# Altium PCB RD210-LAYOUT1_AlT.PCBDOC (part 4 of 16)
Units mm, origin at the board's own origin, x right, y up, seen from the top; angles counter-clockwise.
Board outline 330 x 300 mm, 6 copper layers (TOP, Mid-Layer 1, Mid-Layer 2, Mid-Layer 3, Mid-Layer 4, BOTTOM), stack 1.422 mm thick; 981 components, 463 nets, 2326 pads, 12534 vias.
Unrouted connection lines stored in the file: 6.
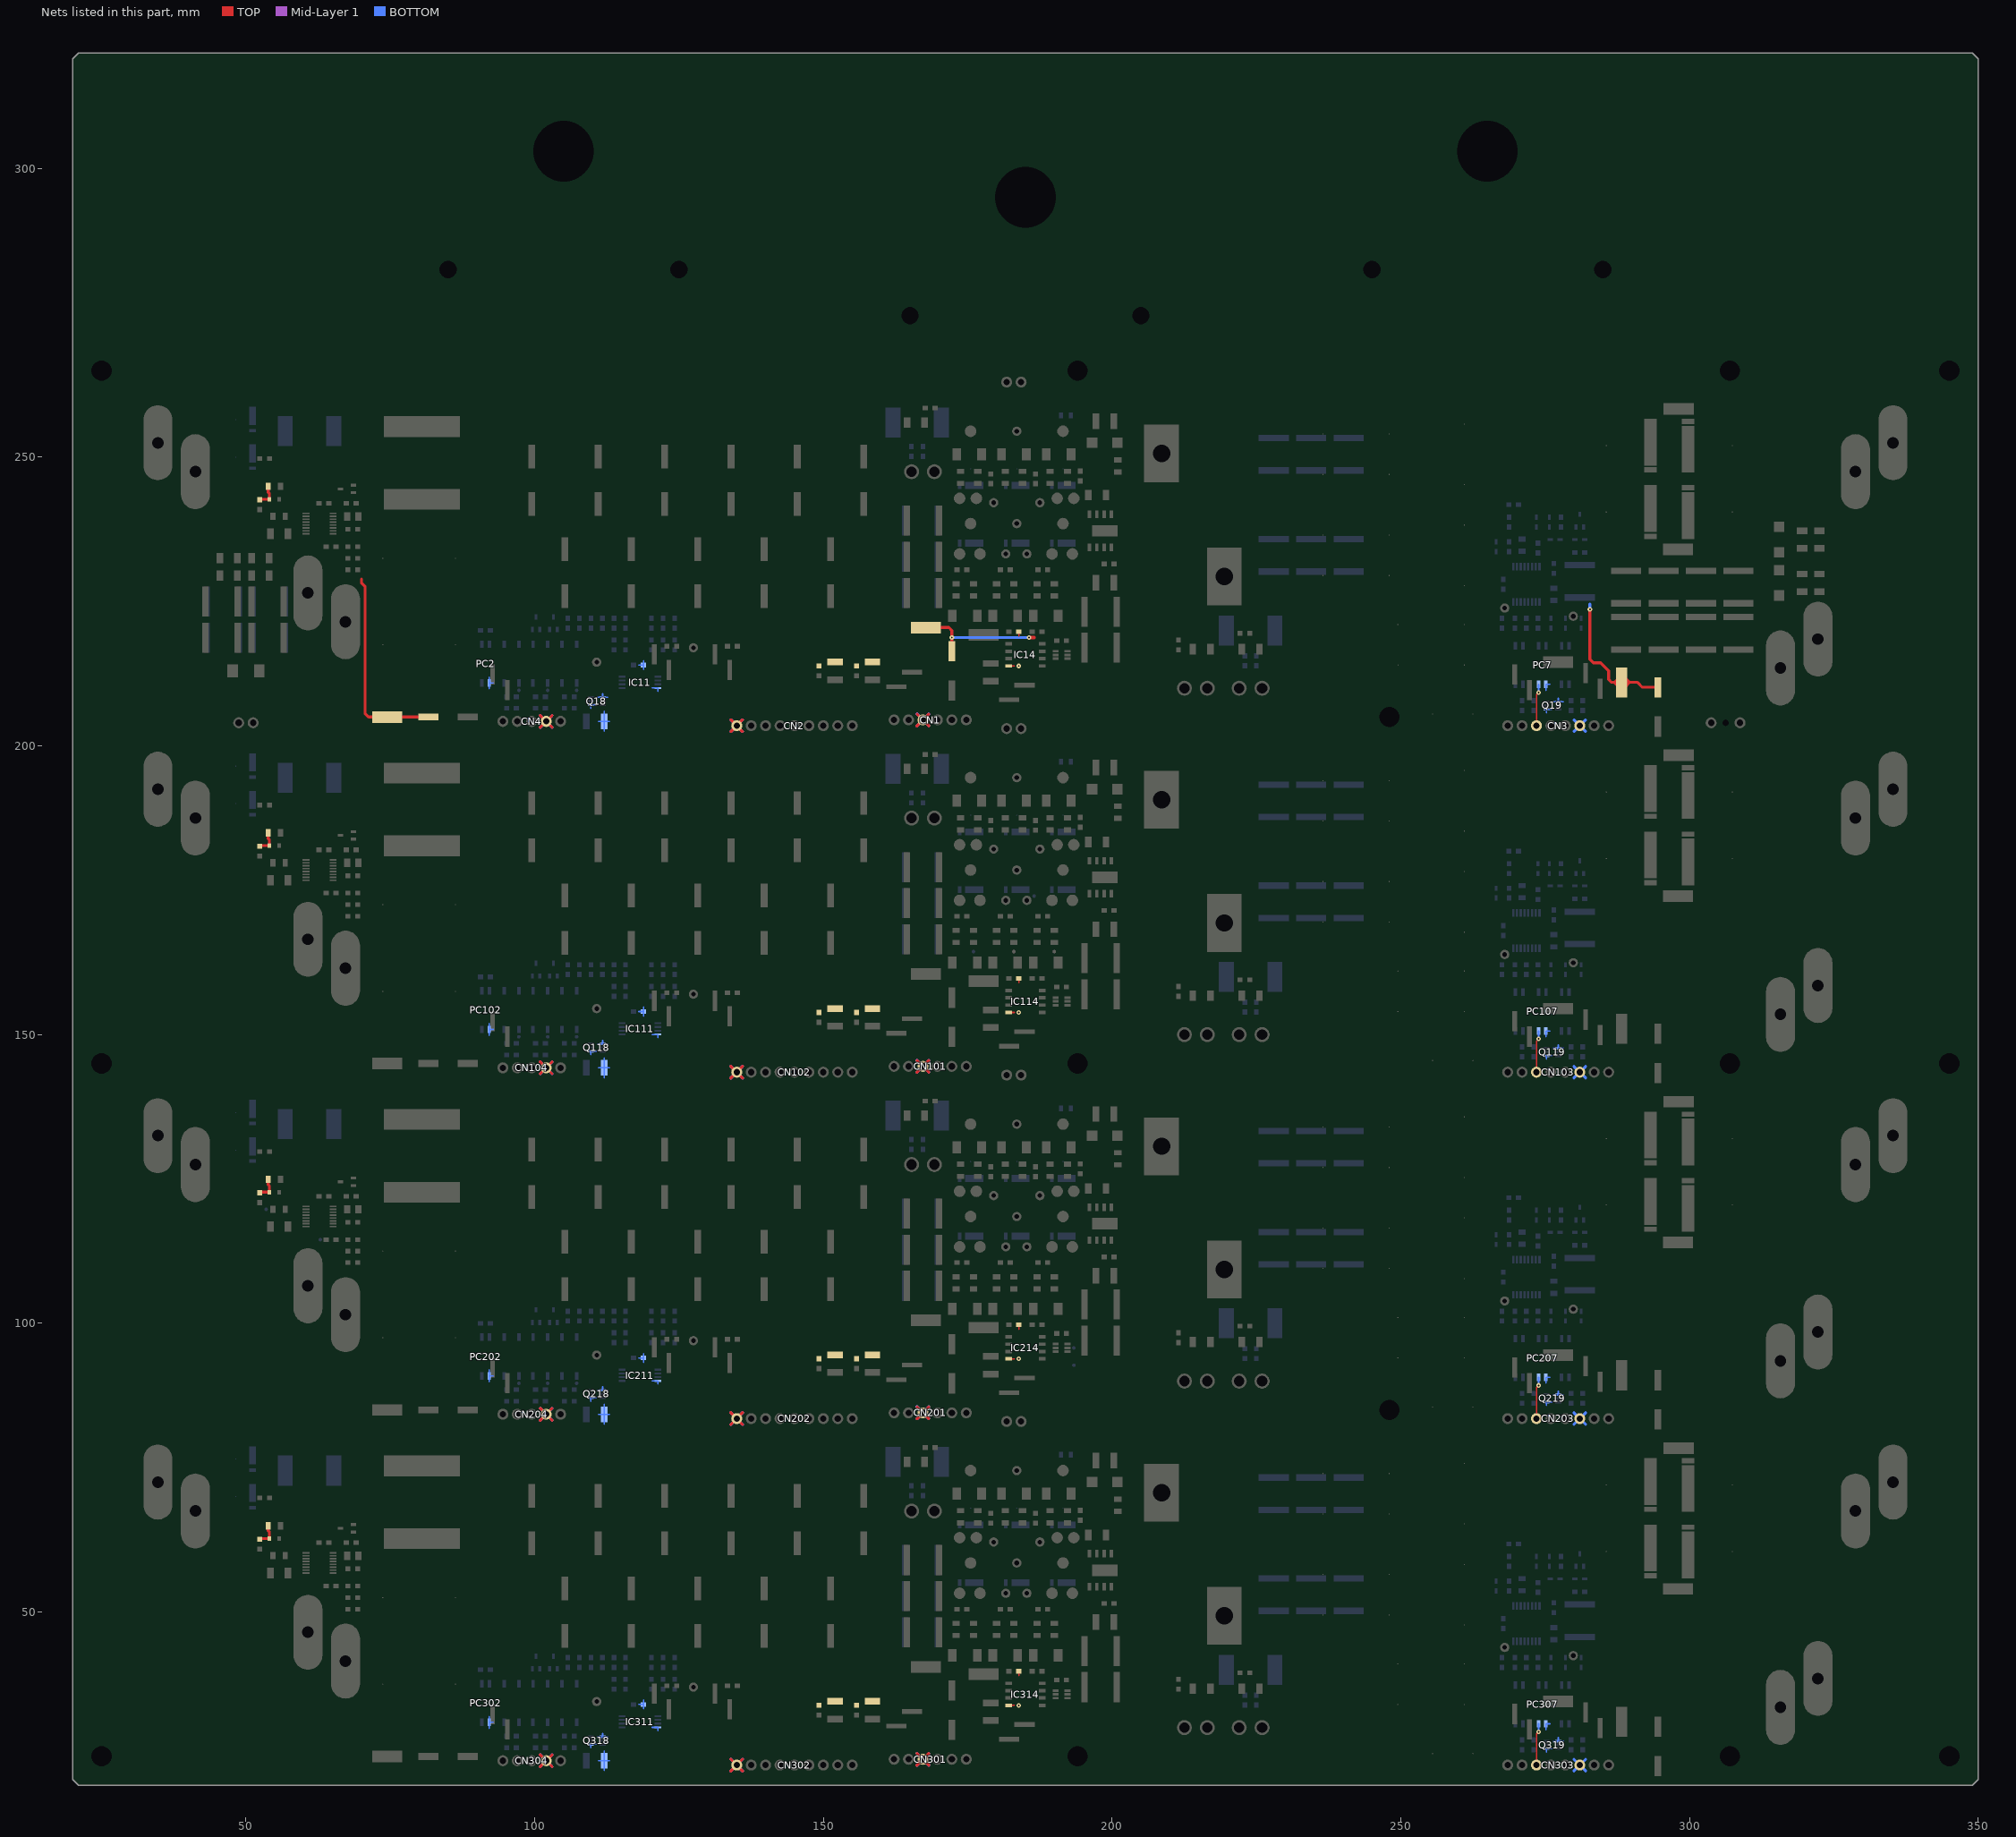
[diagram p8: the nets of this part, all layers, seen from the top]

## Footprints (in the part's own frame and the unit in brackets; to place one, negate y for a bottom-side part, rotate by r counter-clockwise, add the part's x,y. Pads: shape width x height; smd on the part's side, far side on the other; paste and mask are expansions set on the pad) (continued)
S2P_CE-10.3x10.3x12.6-PX11+35 [mm] "KC00080BKP"
  rect 4.1x1.2 smd paste-4.1 mask+0: 1(-4.1,0) 2(4.1,0)
S2P_CE-10.3x10.3x12.6-PX11+36 [mm] "KC00080BKP"
  rect 4.1x1.2 smd paste-4.1 mask+0: 1(-4.1,0) 2(4.1,0)
S2P_CE-10.3x10.3x12.6-PX11+37 [mm] "KC00080BKP"
  rect 4.1x1.2 smd paste-4.1 mask+0: 1(-4.1,0) 2(4.1,0)
S2P_CE-10.3x10.3x12.6-PX11+38 [mm] "KC00080BKP"
  rect 4.1x1.2 smd paste-4.1 mask+0: 1(-4.1,0) 2(4.1,0)
S2P_CE-10.3x10.3x12.6-PX11+39 [mm] "KC00080BKP"
  rect 4.1x1.2 smd paste-4.1 mask+0: 1(-4.1,0) 2(4.1,0)
S2P_CE-10.3x10.3x12.6-PX11+40 [mm] "KC00080BKP"
  rect 4.1x1.2 smd paste-4.1 mask+0: 1(-4.1,0) 2(4.1,0)
S2P_CE-10.3x10.3x12.6-PX11+41 [mm] "KC00080BKP"
  rect 4.1x1.2 smd paste-4.1 mask+0: 1(-4.1,0) 2(4.1,0)
S2P_CE-10.3x10.3x12.6-PX11+42 [mm] "KC00080BKP"
  rect 4.1x1.2 smd paste-4.1 mask+0: 1(-4.1,0) 2(4.1,0)
S2P_CE-10.3x10.3x12.6-PX11+43 [mm] "KC00080BKP"
  rect 4.1x1.2 smd paste-4.1 mask+0: 1(-4.1,0) 2(4.1,0)
S2P_D-3.8x2.4x1-PX4.7 [mm] "KC00080BKP"
  rect 1.5x2.1 smd paste-2.1 mask+0: 1(-2.15,0) 2(2.15,0)
S2P_D-3.8x2.4x1-PX4.7+1 [mm] "KC00080BKP"
  rect 1.5x2.1 smd paste-2.1 mask+0: 1(-2.15,0) 2(2.15,0)
S2P_D-3.8x2.4x1-PX4.7+2 [mm] "KC00080BKP"
  rect 1.5x2.1 smd paste-2.1 mask+0: 1(-2.15,0) 2(2.15,0)
S2P_D-3.8x2.4x1-PX4.7+3 [mm] "KC00080BKP"
  rect 1.5x2.1 smd paste-2.1 mask+0: 1(-2.15,0) 2(2.15,0)
S2P_D-3.8x2.4x1-PX4.7+4 [mm] "KC00080BKP"
  rect 1.5x2.1 smd paste-2.1 mask+0: 1(-2.15,0) 2(2.15,0)
S2P_D-3.8x2.4x1-PX4.7+5 [mm] "KC00080BKP"
  rect 1.5x2.1 smd paste-2.1 mask+0: 1(-2.15,0) 2(2.15,0)
S2P_D-3.8x2.4x1-PX4.7+6 [mm] "KC00080BKP"
  rect 1.5x2.1 smd paste-2.1 mask+0: 1(-2.15,0) 2(2.15,0)
S2P_D-3.8x2.4x1-PX4.7+7 [mm] "KC00080BKP"
  rect 1.5x2.1 smd paste-2.1 mask+0: 1(-2.15,0) 2(2.15,0)
S2P_D-3.8x2.4x1-PX4.7+8 [mm] "KC00080BKP"
  rect 1.5x2.1 smd paste-2.1 mask+0: 1(-2.15,0) 2(2.15,0)
S2P_D-3.8x2.4x1-PX4.7+9 [mm] "KC00080BKP"
  rect 1.5x2.1 smd paste-2.1 mask+0: 1(-2.15,0) 2(2.15,0)
S2P_D-3.8x2.4x1-PX4.7+10 [mm] "KC00080BKP"
  rect 1.5x2.1 smd paste-2.1 mask+0: 1(-2.15,0) 2(2.15,0)
S2P_D-3.8x2.4x1-PX4.7+11 [mm] "KC00080BKP"
  rect 1.5x2.1 smd paste-2.1 mask+0: 1(-2.15,0) 2(2.15,0)
S2P_D-3.8x2.4x1-PX4.7+12 [mm] "KC00080BKP"
  rect 1.5x2.1 smd paste-2.1 mask+0: 1(-2.15,0) 2(2.15,0)
S2P_D-3.8x2.4x1-PX4.7+13 [mm] "KC00080BKP"
  rect 1.5x2.1 smd paste-2.1 mask+0: 1(-2.15,0) 2(2.15,0)
S2P_D-3.8x2.4x1-PX4.7+14 [mm] "KC00080BKP"
  rect 1.5x2.1 smd paste-2.1 mask+0: 1(-2.15,0) 2(2.15,0)
S2P_D-3.8x2.4x1-PX4.7+15 [mm] "KC00080BKP"
  rect 1.5x2.1 smd paste-2.1 mask+0: 1(-2.15,0) 2(2.15,0)
S2P_D-3.8x2.4x1-PX4.7+16 [mm] "KC00080BKP"
  rect 1.5x2.1 smd paste-2.1 mask+0: 1(-2.15,0) 2(2.15,0)
S2P_D-3.8x2.4x1-PX4.7+17 [mm] "KC00080BKP"
  rect 1.5x2.1 smd paste-2.1 mask+0: 1(-2.15,0) 2(2.15,0)
S2P_D-3.8x2.4x1-PX4.7+18 [mm] "KC00080BKP"
  rect 1.5x2.1 smd paste-2.1 mask+0: 1(-2.15,0) 2(2.15,0)
S2P_D-3.8x2.4x1-PX4.7+19 [mm] "KC00080BKP"
  rect 1.5x2.1 smd paste-2.1 mask+0: 1(-2.15,0) 2(2.15,0)
S2P_D-3.8x2.4x1-PX4.7+20 [mm] "KC00080BKP"
  rect 1.5x2.1 smd paste-2.1 mask+0: 1(-2.15,0) 2(2.15,0)
S2P_D-3.8x2.4x1-PX4.7+21 [mm] "KC00080BKP"
  rect 1.5x2.1 smd paste-2.1 mask+0: 1(-2.15,0) 2(2.15,0)
S2P_D-3.8x2.4x1-PX4.7+22 [mm] "KC00080BKP"
  rect 1.5x2.1 smd paste-2.1 mask+0: 1(-2.15,0) 2(2.15,0)
S2P_D-3.8x2.4x1-PX4.7+23 [mm] "KC00080BKP"
  rect 1.5x2.1 smd paste-2.1 mask+0: 1(-2.15,0) 2(2.15,0)
S2P_D-4.3x3.6x2.45-PX5.4 [mm] "KC00080BKP"
  rect 1.8x2.2 smd paste-2.2 mask+0: 1(-2.3,0) 2(2.3,0)
S2P_D-4.32x2.6x2.2-PX5.21 [mm] "KC00080BKP"
  rect 1.8x1.8 smd paste-1.8 mask+0: 1(-2.2,0) 2(2.2,0)
S2P_D-4.32x2.6x2.2-PX5.21+1 [mm] "KC00080BKP"
  rect 1.8x1.8 smd paste-1.8 mask+0: 1(-2.2,0) 2(2.2,0)
S2P_D-4.32x2.6x2.2-PX5.21+2 [mm] "KC00080BKP"
  rect 1.8x1.8 smd paste-1.8 mask+0: 1(-2.2,0) 2(2.2,0)
S2P_D-4.32x2.6x2.2-PX5.21+3 [mm] "KC00080BKP"
  rect 1.8x1.8 smd paste-1.8 mask+0: 1(-2.2,0) 2(2.2,0)
S2P_R-1.6x0.8x0.45-PX1.6 [mm] "KC00080BKP"
  rect 0.9x0.8 smd paste-0.9 mask+0: 1(-0.85,0) 2(0.85,0)
S2P_R-1.6x0.8x0.45-PX1.6+1 [mm] "KC00080BKP"
  rect 0.9x0.8 smd paste-0.9 mask+0: 1(-0.85,0) 2(0.85,0)
S2P_R-1.6x0.8x0.45-PX1.6+2 [mm] "KC00080BKP"
  rect 0.9x0.8 smd paste-0.9 mask+0: 1(-0.85,0) 2(0.85,0)
S2P_R-1.6x0.8x0.45-PX1.6+3 [mm] "KC00080BKP"
  rect 0.9x0.8 smd paste-0.9 mask+0: 1(-0.85,0) 2(0.85,0)
S2P_R-1.6x0.8x0.45-PX1.6+4 [mm] "KC00080BKP"
  rect 0.9x0.8 smd paste-0.9 mask+0: 1(-0.85,0) 2(0.85,0)
S2P_R-1.6x0.8x0.45-PX1.6+5 [mm] "KC00080BKP"
  rect 0.9x0.8 smd paste-0.9 mask+0: 1(-0.85,0) 2(0.85,0)
S2P_R-1.6x0.8x0.45-PX1.6+6 [mm] "KC00080BKP"
  rect 0.9x0.8 smd paste-0.9 mask+0: 1(-0.85,0) 2(0.85,0)
S2P_R-1.6x0.8x0.45-PX1.6+7 [mm] "KC00080BKP"
  rect 0.9x0.8 smd paste-0.9 mask+0: 1(-0.85,0) 2(0.85,0)
S2P_R-1.6x0.8x0.45-PX1.6+8 [mm] "KC00080BKP"
  rect 0.9x0.8 smd paste-0.9 mask+0: 1(-0.85,0) 2(0.85,0)
S2P_R-1.6x0.8x0.45-PX1.6+9 [mm] "KC00080BKP"
  rect 0.9x0.8 smd paste-0.9 mask+0: 1(-0.85,0) 2(0.85,0)
S2P_R-1.6x0.8x0.45-PX1.6+10 [mm] "KC00080BKP"
  rect 0.9x0.8 smd paste-0.9 mask+0: 1(-0.85,0) 2(0.85,0)
S2P_R-1.6x0.8x0.45-PX1.6+11 [mm] "KC00080BKP"
  rect 0.9x0.8 smd paste-0.9 mask+0: 1(-0.85,0) 2(0.85,0)
S2P_R-1.6x0.8x0.45-PX1.6+12 [mm] "KC00080BKP"
  rect 0.9x0.8 smd paste-0.9 mask+0: 1(0.85,0) 2(-0.85,0)
S2P_R-1.6x0.8x0.45-PX1.6+13 [mm] "KC00080BKP"
  rect 0.9x0.8 smd paste-0.9 mask+0: 1(0.85,0) 2(-0.85,0)
S2P_R-1.6x0.8x0.45-PX1.6+14 [mm] "KC00080BKP"
  rect 0.9x0.8 smd paste-0.9 mask+0: 1(0.85,0) 2(-0.85,0)
S2P_R-1.6x0.8x0.45-PX1.6+15 [mm] "KC00080BKP"
  rect 0.9x0.8 smd paste-0.9 mask+0: 1(0.85,0) 2(-0.85,0)
S2P_R-1.6x0.8x0.45-PX1.6+16 [mm] "KC00080BKP"
  rect 0.9x0.8 smd paste-0.9 mask+0: 1(0.85,0) 2(-0.85,0)
S2P_R-1.6x0.8x0.45-PX1.6+17 [mm] "KC00080BKP"
  rect 0.9x0.8 smd paste-0.9 mask+0: 1(0.85,0) 2(-0.85,0)
S2P_R-1.6x0.8x0.45-PX1.6+18 [mm] "KC00080BKP"
  rect 0.9x0.8 smd paste-0.9 mask+0: 1(0.85,0) 2(-0.85,0)
S2P_R-1.6x0.8x0.45-PX1.6+19 [mm] "KC00080BKP"
  rect 0.9x0.8 smd paste-0.9 mask+0: 1(0.85,0) 2(-0.85,0)
S2P_R-1.6x0.8x0.45-PX1.6+20 [mm] "KC00080BKP"
  rect 0.9x0.8 smd paste-0.9 mask+0: 1(0.85,0) 2(-0.85,0)
S2P_R-1.6x0.8x0.45-PX1.6+21 [mm] "KC00080BKP"
  rect 0.9x0.8 smd paste-0.9 mask+0: 1(0.85,0) 2(-0.85,0)
S2P_R-1.6x0.8x0.45-PX1.6+22 [mm] "KC00080BKP"
  rect 0.9x0.8 smd paste-0.9 mask+0: 1(0.85,0) 2(-0.85,0)
S2P_R-1.6x0.8x0.45-PX1.6+23 [mm] "KC00080BKP"
  rect 0.9x0.8 smd paste-0.9 mask+0: 1(0.85,0) 2(-0.85,0)
S2P_R-1.6x0.8x0.45-PX1.6+24 [mm] "KC00080BKP"
  rect 0.9x0.8 smd paste-0.9 mask+0: 1(0.85,0) 2(-0.85,0)
S2P_R-1.6x0.8x0.45-PX1.6+25 [mm] "KC00080BKP"
  rect 0.9x0.8 smd paste-0.9 mask+0: 1(0.85,0) 2(-0.85,0)
S2P_R-1.6x0.8x0.45-PX1.6+26 [mm] "KC00080BKP"
  rect 0.9x0.8 smd paste-0.9 mask+0: 1(0.85,0) 2(-0.85,0)
S2P_R-1.6x0.8x0.45-PX1.6+27 [mm] "KC00080BKP"
  rect 0.9x0.8 smd paste-0.9 mask+0: 1(0.85,0) 2(-0.85,0)
S2P_R-1.6x0.8x0.45-PX1.6+28 [mm] "KC00080BKP"
  rect 0.9x0.8 smd paste-0.9 mask+0: 1(0.85,0) 2(-0.85,0)
S2P_R-1.6x0.8x0.45-PX1.6+29 [mm] "KC00080BKP"
  rect 0.9x0.8 smd paste-0.9 mask+0: 1(0.85,0) 2(-0.85,0)
S2P_R-1.6x0.8x0.45-PX1.6+30 [mm] "KC00080BKP"
  rect 0.9x0.8 smd paste-0.9 mask+0: 1(0.85,0) 2(-0.85,0)
S2P_R-1.6x0.8x0.45-PX1.6+31 [mm] "KC00080BKP"
  rect 0.9x0.8 smd paste-0.9 mask+0: 1(0.85,0) 2(-0.85,0)
S2P_R-1.6x0.8x0.45-PX1.6+32 [mm] "KC00080BKP"
  rect 0.9x0.8 smd paste-0.9 mask+0: 1(0.85,0) 2(-0.85,0)
S2P_R-1.6x0.8x0.45-PX1.6+33 [mm] "KC00080BKP"
  rect 0.9x0.8 smd paste-0.9 mask+0: 1(0.85,0) 2(-0.85,0)
S2P_R-1.6x0.8x0.45-PX1.6+34 [mm] "KC00080BKP"
  rect 0.9x0.8 smd paste-0.9 mask+0: 1(0.85,0) 2(-0.85,0)
S2P_R-1.6x0.8x0.45-PX1.6+35 [mm] "KC00080BKP"
  rect 0.9x0.8 smd paste-0.9 mask+0: 1(0.85,0) 2(-0.85,0)
S2P_R-1.6x0.8x0.45-PX1.6+36 [mm] "KC00080BKP"
  rect 0.9x0.8 smd paste-0.9 mask+0: 1(0.85,0) 2(-0.85,0)
S2P_R-1.6x0.8x0.45-PX1.6+37 [mm] "KC00080BKP"
  rect 0.9x0.8 smd paste-0.9 mask+0: 1(0.85,0) 2(-0.85,0)
S2P_R-1.6x0.8x0.45-PX1.6+38 [mm] "KC00080BKP"
  rect 0.9x0.8 smd paste-0.9 mask+0: 1(0.85,0) 2(-0.85,0)
S2P_R-1.6x0.8x0.45-PX1.6+39 [mm] "KC00080BKP"
  rect 0.9x0.8 smd paste-0.9 mask+0: 1(0.85,0) 2(-0.85,0)
S2P_R-1.6x0.8x0.45-PX1.6+40 [mm] "KC00080BKP"
  rect 0.9x0.8 smd paste-0.9 mask+0: 1(0.85,0) 2(-0.85,0)
S2P_R-1.6x0.8x0.45-PX1.6+41 [mm] "KC00080BKP"
  rect 0.9x0.8 smd paste-0.9 mask+0: 1(0.85,0) 2(-0.85,0)
S2P_R-1.6x0.8x0.45-PX1.6+42 [mm] "KC00080BKP"
  rect 0.9x0.8 smd paste-0.9 mask+0: 1(0.85,0) 2(-0.85,0)
S2P_R-1.6x0.8x0.45-PX1.6+43 [mm] "KC00080BKP"
  rect 0.9x0.8 smd paste-0.9 mask+0: 1(0.85,0) 2(-0.85,0)
S2P_R-1.6x0.8x0.45-PX1.6+44 [mm] "KC00080BKP"
  rect 0.9x0.8 smd paste-0.9 mask+0: 1(0.85,0) 2(-0.85,0)
S2P_R-1.6x0.8x0.45-PX1.6+45 [mm] "KC00080BKP"
  rect 0.9x0.8 smd paste-0.9 mask+0: 1(0.85,0) 2(-0.85,0)
S2P_R-1.6x0.8x0.45-PX1.6+46 [mm] "KC00080BKP"
  rect 0.9x0.8 smd paste-0.9 mask+0: 1(0.85,0) 2(-0.85,0)
S2P_R-1.6x0.8x0.45-PX1.6+47 [mm] "KC00080BKP"
  rect 0.9x0.8 smd paste-0.9 mask+0: 1(0.85,0) 2(-0.85,0)
S2P_R-1.6x0.8x0.45-PX1.6+48 [mm] "KC00080BKP"
  rect 0.9x0.8 smd paste-0.9 mask+0: 1(0.85,0) 2(-0.85,0)
S2P_R-1.6x0.8x0.45-PX1.6+49 [mm] "KC00080BKP"
  rect 0.9x0.8 smd paste-0.9 mask+0: 1(0.85,0) 2(-0.85,0)
S2P_R-1.6x0.8x0.45-PX1.6+50 [mm] "KC00080BKP"
  rect 0.9x0.8 smd paste-0.9 mask+0: 1(0.85,0) 2(-0.85,0)
S2P_R-1.6x0.8x0.45-PX1.6+51 [mm] "KC00080BKP"
  rect 0.9x0.8 smd paste-0.9 mask+0: 1(0.85,0) 2(-0.85,0)
S2P_R-1.6x0.8x0.45-PX1.6+52 [mm] "KC00080BKP"
  rect 0.9x0.8 smd paste-0.9 mask+0: 1(0.85,0) 2(-0.85,0)
S2P_R-1.6x0.8x0.45-PX1.6+53 [mm] "KC00080BKP"
  rect 0.9x0.8 smd paste-0.9 mask+0: 1(0.85,0) 2(-0.85,0)
S2P_R-1.6x0.8x0.45-PX1.6+54 [mm] "KC00080BKP"
  rect 0.9x0.8 smd paste-0.9 mask+0: 1(0.85,0) 2(-0.85,0)
S2P_R-1.6x0.8x0.45-PX1.6+55 [mm] "KC00080BKP"
  rect 0.9x0.8 smd paste-0.9 mask+0: 1(0.85,0) 2(-0.85,0)
S2P_R-1.6x0.8x0.45-PX1.6+56 [mm] "KC00080BKP"
  rect 0.9x0.8 smd paste-0.9 mask+0: 1(-0.85,0) 2(0.85,0)
S2P_R-1.6x0.8x0.45-PX1.6+57 [mm] "KC00080BKP"
  rect 0.9x0.8 smd paste-0.9 mask+0: 1(-0.85,0) 2(0.85,0)
S2P_R-1.6x0.8x0.45-PX1.6+58 [mm] "KC00080BKP"
  rect 0.9x0.8 smd paste-0.9 mask+0: 1(-0.85,0) 2(0.85,0)
S2P_R-1.6x0.8x0.45-PX1.6+59 [mm] "KC00080BKP"
  rect 0.9x0.8 smd paste-0.9 mask+0: 1(-0.85,0) 2(0.85,0)
S2P_R-2x1.25x0.5-PX2 [mm] "KC00080BKP"
  rect 0.9x1.25 smd paste-1.25 mask+0: 1(-1.05,0) 2(1.05,0)
S2P_R-2x1.25x0.5-PX2+1 [mm] "KC00080BKP"
  rect 0.9x1.25 smd paste-1.25 mask+0: 1(-1.05,0) 2(1.05,0)
S2P_R-2x1.25x0.5-PX2+2 [mm] "KC00080BKP"
  rect 0.9x1.25 smd paste-1.25 mask+0: 1(-1.05,0) 2(1.05,0)
S2P_R-2x1.25x0.5-PX2+3 [mm] "KC00080BKP"
  rect 0.9x1.25 smd paste-1.25 mask+0: 1(-1.05,0) 2(1.05,0)
S2P_R-2x1.25x0.5-PX2+4 [mm] "KC00080BKP"
  rect 0.9x1.25 smd paste-1.25 mask+0: 1(-1.05,0) 2(1.05,0)
S2P_R-2x1.25x0.5-PX2+5 [mm] "KC00080BKP"
  rect 0.9x1.25 smd paste-1.25 mask+0: 1(-1.05,0) 2(1.05,0)
S2P_R-2x1.25x0.5-PX2+6 [mm] "KC00080BKP"
  rect 0.9x1.25 smd paste-1.25 mask+0: 1(-1.05,0) 2(1.05,0)
S2P_R-2x1.25x0.5-PX2+7 [mm] "KC00080BKP"
  rect 0.9x1.25 smd paste-1.25 mask+0: 1(-1.05,0) 2(1.05,0)
S2P_R-10x5.2x1.3-PX10 [mm] "KC00080BKP"
  rect 2.6x5.2 smd paste-5.2 mask+0: 1(4.2,0) 2(-4.2,0)
S2P_R-10x5.2x1.3-PX10+1 [mm] "KC00080BKP"
  rect 2.6x5.2 smd paste-5.2 mask+0: 1(4.2,0) 2(-4.2,0)
S2P_R-10x5.2x1.3-PX10+2 [mm] "KC00080BKP"
  rect 2.6x5.2 smd paste-5.2 mask+0: 1(4.2,0) 2(-4.2,0)
S2P_R-10x5.2x1.3-PX10+3 [mm] "KC00080BKP"
  rect 2.6x5.2 smd paste-5.2 mask+0: 1(4.2,0) 2(-4.2,0)
S2P_R-10x5.2x1.3-PX10+4 [mm] "KC00080BKP"
  rect 2.6x5.2 smd paste-5.2 mask+0: 1(4.2,0) 2(-4.2,0)
S2P_R-10x5.2x1.3-PX10+5 [mm] "KC00080BKP"
  rect 2.6x5.2 smd paste-5.2 mask+0: 1(4.2,0) 2(-4.2,0)
S2P_R-10x5.2x1.3-PX10+6 [mm] "KC00080BKP"
  rect 2.6x5.2 smd paste-5.2 mask+0: 1(4.2,0) 2(-4.2,0)
S2P_R-10x5.2x1.3-PX10+7 [mm] "KC00080BKP"
  rect 2.6x5.2 smd paste-5.2 mask+0: 1(4.2,0) 2(-4.2,0)
S2P_R-10x5.2x1.3-PX10+8 [mm] "KC00080BKP"
  rect 2.6x5.2 smd paste-5.2 mask+0: 1(4.2,0) 2(-4.2,0)
S2P_R-10x5.2x1.3-PX10+9 [mm] "KC00080BKP"
  rect 2.6x5.2 smd paste-5.2 mask+0: 1(4.2,0) 2(-4.2,0)
S2P_R-10x5.2x1.3-PX10+10 [mm] "KC00080BKP"
  rect 2.6x5.2 smd paste-5.2 mask+0: 1(4.2,0) 2(-4.2,0)
S2P_R-10x5.2x1.3-PX10+11 [mm] "KC00080BKP"
  rect 2.6x5.2 smd paste-5.2 mask+0: 1(4.2,0) 2(-4.2,0)
S2P_ZD-0.8x1.2x0.6-PY1.6 [mm] "KC00080BKP"
  rect 0.5x0.9 smd paste-0.9 mask+0: 1(0,0.85) 2(0,-0.85)
S2P_ZD-0.8x1.2x0.6-PY1.6+1 [mm] "KC00080BKP"
  rect 0.5x0.9 smd paste-0.9 mask+0: 1(0,0.85) 2(0,-0.85)
S2P_ZD-0.8x1.2x0.6-PY1.6+2 [mm] "KC00080BKP"
  rect 0.5x0.9 smd paste-0.9 mask+0: 1(0,0.85) 2(0,-0.85)
S2P_ZD-0.8x1.2x0.6-PY1.6+3 [mm] "KC00080BKP"
  rect 0.5x0.9 smd paste-0.9 mask+0: 1(0,0.85) 2(0,-0.85)
S2P_ZD-0.8x1.2x0.6-PY1.6+4 [mm] "KC00080BKP"
  rect 0.5x0.9 smd paste-0.9 mask+0: 1(0,0.85) 2(0,-0.85)
S2P_ZD-0.8x1.2x0.6-PY1.6+5 [mm] "KC00080BKP"
  rect 0.5x0.9 smd paste-0.9 mask+0: 1(0,0.85) 2(0,-0.85)
S2P_ZD-0.8x1.2x0.6-PY1.6+6 [mm] "KC00080BKP"
  rect 0.5x0.9 smd paste-0.9 mask+0: 1(0,0.85) 2(0,-0.85)
S2P_ZD-0.8x1.2x0.6-PY1.6+7 [mm] "KC00080BKP"
  rect 0.5x0.9 smd paste-0.9 mask+0: 1(0,0.85) 2(0,-0.85)
S3P_FET-5x5x1-PX1.27-PY6 [mm] "KC00080BKP"
  round 0.178 smd paste-0.178 mask+0: D(0,0)
  rect 0.6x1.2 smd paste-1.2 mask+0: G(-1.905,2.9)
  rect 3.14x1.2 smd paste-3.14 mask+0: S(0.64,2.9)
S3P_FET-5x5x1-PX1.27-PY6+1 [mm] "KC00080BKP"
  round 0.178 smd paste-0.178 mask+0: D(0,0)
  rect 0.6x1.2 smd paste-1.2 mask+0: G(-1.905,2.9)
  rect 3.14x1.2 smd paste-3.14 mask+0: S(0.64,2.9)
S3P_FET-5x5x1-PX1.27-PY6+2 [mm] "KC00080BKP"
  round 0.178 smd paste-0.178 mask+0: D(0,0)
  rect 0.6x1.2 smd paste-1.2 mask+0: G(-1.905,2.9)
  rect 3.14x1.2 smd paste-3.14 mask+0: S(0.64,2.9)
S3P_FET-5x5x1-PX1.27-PY6+3 [mm] "KC00080BKP"
  round 0.178 smd paste-0.178 mask+0: D(0,0)
  rect 0.6x1.2 smd paste-1.2 mask+0: G(-1.905,2.9)
  rect 3.14x1.2 smd paste-3.14 mask+0: S(0.64,2.9)
S3P_FET-5x5x1-PX1.27-PY6+4 [mm] "KC00080BKP"
  round 0.178 smd paste-0.178 mask+0: D(0,0)
  rect 0.6x1.2 smd paste-1.2 mask+0: G(-1.905,2.9)
  rect 3.14x1.2 smd paste-3.14 mask+0: S(0.64,2.9)
S3P_FET-5x5x1-PX1.27-PY6+5 [mm] "KC00080BKP"
  round 0.178 smd paste-0.178 mask+0: D(0,0)
  rect 0.6x1.2 smd paste-1.2 mask+0: G(-1.905,2.9)
  rect 3.14x1.2 smd paste-3.14 mask+0: S(0.64,2.9)
S3P_FET-5x5x1-PX1.27-PY6+6 [mm] "KC00080BKP"
  round 0.178 smd paste-0.178 mask+0: D(0,0)
  rect 0.6x1.2 smd paste-1.2 mask+0: G(-1.905,2.9)
  rect 3.14x1.2 smd paste-3.14 mask+0: S(0.64,2.9)
S3P_FET-5x5x1-PX1.27-PY6+7 [mm] "KC00080BKP"
  round 0.178 smd paste-0.178 mask+0: D(0,0)
  rect 0.6x1.2 smd paste-1.2 mask+0: G(-1.905,2.9)
  rect 3.14x1.2 smd paste-3.14 mask+0: S(0.64,2.9)
S3P_FET-5x5x1-PX1.27-PY6+8 [mm] "KC00080BKP"
  round 0.178 smd paste-0.178 mask+0: D(0,0)
  rect 0.6x1.2 smd paste-1.2 mask+0: G(-1.905,2.9)
  rect 3.14x1.2 smd paste-3.14 mask+0: S(0.64,2.9)
S3P_FET-5x5x1-PX1.27-PY6+9 [mm] "KC00080BKP"
  round 0.178 smd paste-0.178 mask+0: D(0,0)
  rect 0.6x1.2 smd paste-1.2 mask+0: G(-1.905,2.9)
  rect 3.14x1.2 smd paste-3.14 mask+0: S(0.64,2.9)
S3P_FET-5x5x1-PX1.27-PY6+10 [mm] "KC00080BKP"
  round 0.178 smd paste-0.178 mask+0: D(0,0)
  rect 0.6x1.2 smd paste-1.2 mask+0: G(-1.905,2.9)
  rect 3.14x1.2 smd paste-3.14 mask+0: S(0.64,2.9)
S3P_FET-5x5x1-PX1.27-PY6+11 [mm] "KC00080BKP"
  round 0.178 smd paste-0.178 mask+0: D(0,0)
  rect 0.6x1.2 smd paste-1.2 mask+0: G(-1.905,2.9)
  rect 3.14x1.2 smd paste-3.14 mask+0: S(0.64,2.9)
S3P_FET-5x5x1-PX1.27-PY6+12 [mm] "KC00080BKP"
  round 0.178 smd paste-0.178 mask+0: D(0,0)
  rect 0.6x1.2 smd paste-1.2 mask+0: G(-1.905,2.9)
  rect 3.14x1.2 smd paste-3.14 mask+0: S(0.64,2.9)
S3P_FET-5x5x1-PX1.27-PY6+13 [mm] "KC00080BKP"
  round 0.178 smd paste-0.178 mask+0: D(0,0)
  rect 0.6x1.2 smd paste-1.2 mask+0: G(-1.905,2.9)
  rect 3.14x1.2 smd paste-3.14 mask+0: S(0.64,2.9)
S3P_FET-5x5x1-PX1.27-PY6+14 [mm] "KC00080BKP"
  round 0.178 smd paste-0.178 mask+0: D(0,0)
  rect 0.6x1.2 smd paste-1.2 mask+0: G(-1.905,2.9)
  rect 3.14x1.2 smd paste-3.14 mask+0: S(0.64,2.9)
S3P_FET-5x5x1-PX1.27-PY6+15 [mm] "KC00080BKP"
  round 0.178 smd paste-0.178 mask+0: D(0,0)
  rect 0.6x1.2 smd paste-1.2 mask+0: G(-1.905,2.9)
  rect 3.14x1.2 smd paste-3.14 mask+0: S(0.64,2.9)
S3P_FET-5x5x1-PX1.27-PY6+16 [mm] "KC00080BKP"
  round 0.178 smd paste-0.178 mask+0: D(0,0)
  rect 0.6x1.2 smd paste-1.2 mask+0: G(-1.905,2.9)
  rect 3.14x1.2 smd paste-3.14 mask+0: S(0.64,2.9)
S3P_FET-5x5x1-PX1.27-PY6+17 [mm] "KC00080BKP"
  round 0.178 smd paste-0.178 mask+0: D(0,0)
  rect 0.6x1.2 smd paste-1.2 mask+0: G(-1.905,2.9)
  rect 3.14x1.2 smd paste-3.14 mask+0: S(0.64,2.9)
S3P_FET-5x5x1-PX1.27-PY6+18 [mm] "KC00080BKP"
  round 0.178 smd paste-0.178 mask+0: D(0,0)
  rect 0.6x1.2 smd paste-1.2 mask+0: G(-1.905,2.9)
  rect 3.14x1.2 smd paste-3.14 mask+0: S(0.64,2.9)
S3P_FET-5x5x1-PX1.27-PY6+19 [mm] "KC00080BKP"
  round 0.178 smd paste-0.178 mask+0: D(0,0)
  rect 0.6x1.2 smd paste-1.2 mask+0: G(-1.905,2.9)
  rect 3.14x1.2 smd paste-3.14 mask+0: S(0.64,2.9)
S3P_FET-5x5x1-PX1.27-PY6+20 [mm] "KC00080BKP"
  round 0.178 smd paste-0.178 mask+0: D(0,0)
  rect 0.6x1.2 smd paste-1.2 mask+0: G(-1.905,2.9)
  rect 3.14x1.2 smd paste-3.14 mask+0: S(0.64,2.9)
S3P_FET-5x5x1-PX1.27-PY6+21 [mm] "KC00080BKP"
  round 0.178 smd paste-0.178 mask+0: D(0,0)
  rect 0.6x1.2 smd paste-1.2 mask+0: G(-1.905,2.9)
  rect 3.14x1.2 smd paste-3.14 mask+0: S(0.64,2.9)
S3P_FET-5x5x1-PX1.27-PY6+22 [mm] "KC00080BKP"
  round 0.178 smd paste-0.178 mask+0: D(0,0)
  rect 0.6x1.2 smd paste-1.2 mask+0: G(-1.905,2.9)
  rect 3.14x1.2 smd paste-3.14 mask+0: S(0.64,2.9)
S3P_FET-5x5x1-PX1.27-PY6+23 [mm] "KC00080BKP"
  round 0.178 smd paste-0.178 mask+0: D(0,0)
  rect 0.6x1.2 smd paste-1.2 mask+0: G(-1.905,2.9)
  rect 3.14x1.2 smd paste-3.14 mask+0: S(0.64,2.9)
S3P_FET-5x5x1-PX1.27-PY6+24 [mm] "KC00080BKP"
  round 0.178 smd paste-0.178 mask+0: D(0,0)
  rect 0.6x1.2 smd paste-1.2 mask+0: G(-1.905,2.9)
  rect 3.14x1.2 smd paste-3.14 mask+0: S(0.64,2.9)
S3P_FET-5x5x1-PX1.27-PY6+25 [mm] "KC00080BKP"
  round 0.178 smd paste-0.178 mask+0: D(0,0)
  rect 0.6x1.2 smd paste-1.2 mask+0: G(-1.905,2.9)
  rect 3.14x1.2 smd paste-3.14 mask+0: S(0.64,2.9)
S3P_FET-5x5x1-PX1.27-PY6+26 [mm] "KC00080BKP"
  round 0.178 smd paste-0.178 mask+0: D(0,0)
  rect 0.6x1.2 smd paste-1.2 mask+0: G(-1.905,2.9)
  rect 3.14x1.2 smd paste-3.14 mask+0: S(0.64,2.9)
S3P_FET-5x5x1-PX1.27-PY6+27 [mm] "KC00080BKP"
  round 0.178 smd paste-0.178 mask+0: D(0,0)
  rect 0.6x1.2 smd paste-1.2 mask+0: G(-1.905,2.9)
  rect 3.14x1.2 smd paste-3.14 mask+0: S(0.64,2.9)
S3P_FET-5x5x1-PX1.27-PY6+28 [mm] "KC00080BKP"
  round 0.178 smd paste-0.178 mask+0: D(0,0)
  rect 0.6x1.2 smd paste-1.2 mask+0: G(-1.905,2.9)
  rect 3.14x1.2 smd paste-3.14 mask+0: S(0.64,2.9)
S3P_FET-5x5x1-PX1.27-PY6+29 [mm] "KC00080BKP"
  round 0.178 smd paste-0.178 mask+0: D(0,0)
  rect 0.6x1.2 smd paste-1.2 mask+0: G(-1.905,2.9)
  rect 3.14x1.2 smd paste-3.14 mask+0: S(0.64,2.9)
S3P_FET-5x5x1-PX1.27-PY6+30 [mm] "KC00080BKP"
  round 0.178 smd paste-0.178 mask+0: D(0,0)
  rect 0.6x1.2 smd paste-1.2 mask+0: G(-1.905,2.9)
  rect 3.14x1.2 smd paste-3.14 mask+0: S(0.64,2.9)
S3P_FET-5x5x1-PX1.27-PY6+31 [mm] "KC00080BKP"
  round 0.178 smd paste-0.178 mask+0: D(0,0)
  rect 0.6x1.2 smd paste-1.2 mask+0: G(-1.905,2.9)
  rect 3.14x1.2 smd paste-3.14 mask+0: S(0.64,2.9)
S3P_Q-2.0x1.25x0.9-PX0.65-PY2.1 [mm] "KC00080BKP"
  rect 0.5x0.9 smd paste-0.9 mask+0: 1(0.65,1.1) 2(-0.65,1.1) 3(0,-1.1)
S3P_Q-2.0x1.25x0.9-PX0.65-PY2.1+1 [mm] "KC00080BKP"
  rect 0.5x0.9 smd paste-0.9 mask+0: 1(0.65,1.1) 2(-0.65,1.1) 3(0,-1.1)
S3P_Q-2.0x1.25x0.9-PX0.65-PY2.1+2 [mm] "KC00080BKP"
  rect 0.5x0.9 smd paste-0.9 mask+0: 1(0.65,1.1) 2(-0.65,1.1) 3(0,-1.1)
S3P_Q-2.0x1.25x0.9-PX0.65-PY2.1+3 [mm] "KC00080BKP"
  rect 0.5x0.9 smd paste-0.9 mask+0: 1(0.65,1.1) 2(-0.65,1.1) 3(0,-1.1)
S3P_Q-2x1.7x0.75-PX0.65-2.1 [mm] "KC00080BKP"
  rect 0.5x0.9 smd paste-0.9 mask+0: 1(0.65,1.1) 2(-0.65,1.1) 3(0,-1.1)
S3P_Q-2x1.7x0.75-PX0.65-2.1+1 [mm] "KC00080BKP"
  rect 0.5x0.9 smd paste-0.9 mask+0: 1(0.65,1.1) 2(-0.65,1.1) 3(0,-1.1)
S3P_Q-2x1.7x0.75-PX0.65-2.1+2 [mm] "KC00080BKP"
  rect 0.5x0.9 smd paste-0.9 mask+0: 1(0.65,1.1) 2(-0.65,1.1) 3(0,-1.1)
S3P_Q-2x1.7x0.75-PX0.65-2.1+3 [mm] "KC00080BKP"
  rect 0.5x0.9 smd paste-0.9 mask+0: 1(0.65,1.1) 2(-0.65,1.1) 3(0,-1.1)
S3P_Q-2x1.7x0.75-PX0.65-2.1+4 [mm] "KC00080BKP"
  rect 0.5x0.9 smd paste-0.9 mask+0: 1(0.65,1.1) 2(-0.65,1.1) 3(0,-1.1)
S3P_Q-2x1.7x0.75-PX0.65-2.1+5 [mm] "KC00080BKP"
  rect 0.5x0.9 smd paste-0.9 mask+0: 1(0.65,1.1) 2(-0.65,1.1) 3(0,-1.1)
S3P_Q-2x1.7x0.75-PX0.65-2.1+6 [mm] "KC00080BKP"
  rect 0.5x0.9 smd paste-0.9 mask+0: 1(0.65,1.1) 2(-0.65,1.1) 3(0,-1.1)
S3P_Q-2x1.7x0.75-PX0.65-2.1+7 [mm] "KC00080BKP"
  rect 0.5x0.9 smd paste-0.9 mask+0: 1(0.65,1.1) 2(-0.65,1.1) 3(0,-1.1)
S3P_Q-2x1.7x0.75-PX0.65-2.1+8 [mm] "KC00080BKP"
  rect 0.5x0.9 smd paste-0.9 mask+0: 1(-0.65,-1.1) 2(0.65,-1.1) 3(0,1.1)
S3P_Q-2x1.7x0.75-PX0.65-2.1+9 [mm] "KC00080BKP"
  rect 0.5x0.9 smd paste-0.9 mask+0: 1(-0.65,-1.1) 2(0.65,-1.1) 3(0,1.1)
S3P_Q-2x1.7x0.75-PX0.65-2.1+10 [mm] "KC00080BKP"
  rect 0.5x0.9 smd paste-0.9 mask+0: 1(-0.65,-1.1) 2(0.65,-1.1) 3(0,1.1)
S3P_Q-2x1.7x0.75-PX0.65-2.1+11 [mm] "KC00080BKP"
  rect 0.5x0.9 smd paste-0.9 mask+0: 1(-0.65,-1.1) 2(0.65,-1.1) 3(0,1.1)
S3P_Q-9.9x8.5-2.3-PX1.2-PY11.8 [mm] "KC00080BKP"
  rect 0.9x2.2 smd paste-2.2 mask+0: 1(-4.2,-6.25)
  rect 8.1x2.2 smd paste-8.1 mask+0: 2(0.6,-6.25)
  round 0.178 smd paste-0.178 mask+0: 3(0,1.4)
S3P_Q-9.9x8.5-2.3-PX1.2-PY11.8+1 [mm] "KC00080BKP"
  rect 0.9x2.2 smd paste-2.2 mask+0: 1(-4.2,-6.25)
  rect 8.1x2.2 smd paste-8.1 mask+0: 2(0.6,-6.25)
  round 0.178 smd paste-0.178 mask+0: 3(0,1.4)
S3P_Q-9.9x8.5-2.3-PX1.2-PY11.8+2 [mm] "KC00080BKP"
  rect 0.9x2.2 smd paste-2.2 mask+0: 1(-4.2,-6.25)
  rect 8.1x2.2 smd paste-8.1 mask+0: 2(0.6,-6.25)
  round 0.178 smd paste-0.178 mask+0: 3(0,1.4)
S3P_Q-9.9x8.5-2.3-PX1.2-PY11.8+3 [mm] "KC00080BKP"
  rect 0.9x2.2 smd paste-2.2 mask+0: 1(-4.2,-6.25)
  rect 8.1x2.2 smd paste-8.1 mask+0: 2(0.6,-6.25)
  round 0.178 smd paste-0.178 mask+0: 3(0,1.4)
S3P_Q-9.9x8.5-2.3-PX1.2-PY11.8+4 [mm] "KC00080BKP"
  rect 0.9x2.2 smd paste-2.2 mask+0: 1(-4.2,-6.25)
  rect 8.1x2.2 smd paste-8.1 mask+0: 2(0.6,-6.25)
  round 0.178 smd paste-0.178 mask+0: 3(0,1.4)
S3P_Q-9.9x8.5-2.3-PX1.2-PY11.8+5 [mm] "KC00080BKP"
  rect 0.9x2.2 smd paste-2.2 mask+0: 1(-4.2,-6.25)
  rect 8.1x2.2 smd paste-8.1 mask+0: 2(0.6,-6.25)
  round 0.178 smd paste-0.178 mask+0: 3(0,1.4)
S3P_Q-9.9x8.5-2.3-PX1.2-PY11.8+6 [mm] "KC00080BKP"
  rect 0.9x2.2 smd paste-2.2 mask+0: 1(-4.2,-6.25)
  rect 8.1x2.2 smd paste-8.1 mask+0: 2(0.6,-6.25)
  round 0.178 smd paste-0.178 mask+0: 3(0,1.4)
S3P_Q-9.9x8.5-2.3-PX1.2-PY11.8+7 [mm] "KC00080BKP"
  rect 0.9x2.2 smd paste-2.2 mask+0: 1(-4.2,-6.25)
  rect 8.1x2.2 smd paste-8.1 mask+0: 2(0.6,-6.25)
  round 0.178 smd paste-0.178 mask+0: 3(0,1.4)
S3P_Q-9.9x8.5-2.3-PX1.2-PY11.8+8 [mm] "KC00080BKP"
  rect 0.9x2.2 smd paste-2.2 mask+0: 1(-4.2,-6.25)
  rect 8.1x2.2 smd paste-8.1 mask+0: 2(0.6,-6.25)
  round 0.178 smd paste-0.178 mask+0: 3(0,1.4)
S3P_Q-9.9x8.5-2.3-PX1.2-PY11.8+9 [mm] "KC00080BKP"
  rect 0.9x2.2 smd paste-2.2 mask+0: 1(-4.2,-6.25)
  rect 8.1x2.2 smd paste-8.1 mask+0: 2(0.6,-6.25)
  round 0.178 smd paste-0.178 mask+0: 3(0,1.4)
S3P_Q-9.9x8.5-2.3-PX1.2-PY11.8+10 [mm] "KC00080BKP"
  rect 0.9x2.2 smd paste-2.2 mask+0: 1(-4.2,-6.25)
  rect 8.1x2.2 smd paste-8.1 mask+0: 2(0.6,-6.25)
  round 0.178 smd paste-0.178 mask+0: 3(0,1.4)
S3P_Q-9.9x8.5-2.3-PX1.2-PY11.8+11 [mm] "KC00080BKP"
  rect 0.9x2.2 smd paste-2.2 mask+0: 1(-4.2,-6.25)
  rect 8.1x2.2 smd paste-8.1 mask+0: 2(0.6,-6.25)
  round 0.178 smd paste-0.178 mask+0: 3(0,1.4)
S3P_Q-9.9x8.5-2.3-PX1.2-PY11.8+12 [mm] "KC00080BKP"
  rect 0.9x2.2 smd paste-2.2 mask+0: 1(-4.2,-6.25)
  rect 8.1x2.2 smd paste-8.1 mask+0: 2(0.6,-6.25)
  round 0.178 smd paste-0.178 mask+0: 3(0,1.4)
S3P_Q-9.9x8.5-2.3-PX1.2-PY11.8+13 [mm] "KC00080BKP"
  rect 0.9x2.2 smd paste-2.2 mask+0: 1(-4.2,-6.25)
  rect 8.1x2.2 smd paste-8.1 mask+0: 2(0.6,-6.25)
  round 0.178 smd paste-0.178 mask+0: 3(0,1.4)
S3P_Q-9.9x8.5-2.3-PX1.2-PY11.8+14 [mm] "KC00080BKP"
  rect 0.9x2.2 smd paste-2.2 mask+0: 1(-4.2,-6.25)
  rect 8.1x2.2 smd paste-8.1 mask+0: 2(0.6,-6.25)
  round 0.178 smd paste-0.178 mask+0: 3(0,1.4)
S3P_Q-9.9x8.5-2.3-PX1.2-PY11.8+15 [mm] "KC00080BKP"
  rect 0.9x2.2 smd paste-2.2 mask+0: 1(-4.2,-6.25)
  rect 8.1x2.2 smd paste-8.1 mask+0: 2(0.6,-6.25)
  round 0.178 smd paste-0.178 mask+0: 3(0,1.4)
S4P_PC-2.6x4.55?2.1-PX1.27-PY7 [mm] "KC00080BKP"
  rect 0.6x1.3 smd paste-1.3 mask+0: 1(0.635,3.35) 2(-0.65,3.35) 3(-0.635,-3.35) 4(0.635,-3.35)
S4P_PC-2.6x4.55?2.1-PX1.27-PY7+1 [mm] "KC00080BKP"
  rect 0.6x1.3 smd paste-1.3 mask+0: 1(0.635,3.35) 2(-0.65,3.35) 3(-0.635,-3.35) 4(0.635,-3.35)
S4P_PC-2.6x4.55?2.1-PX1.27-PY7+2 [mm] "KC00080BKP"
  rect 0.6x1.3 smd paste-1.3 mask+0: 1(0.635,3.35) 2(-0.65,3.35) 3(-0.635,-3.35) 4(0.635,-3.35)
S4P_PC-2.6x4.55?2.1-PX1.27-PY7+3 [mm] "KC00080BKP"
  rect 0.6x1.3 smd paste-1.3 mask+0: 1(0.635,3.35) 2(-0.65,3.35) 3(-0.635,-3.35) 4(0.635,-3.35)
S4P_PC-2.6x4.55?2.1-PX1.27-PY7+4 [mm] "KC00080BKP"
  rect 0.6x1.3 smd paste-1.3 mask+0: 1(0.635,3.35) 2(-0.65,3.35) 3(-0.635,-3.35) 4(0.635,-3.35)
S4P_PC-2.6x4.55?2.1-PX1.27-PY7+5 [mm] "KC00080BKP"
  rect 0.6x1.3 smd paste-1.3 mask+0: 1(0.635,3.35) 2(-0.65,3.35) 3(-0.635,-3.35) 4(0.635,-3.35)
S4P_PC-2.6x4.55?2.1-PX1.27-PY7+6 [mm] "KC00080BKP"
  rect 0.6x1.3 smd paste-1.3 mask+0: 1(0.635,3.35) 2(-0.65,3.35) 3(-0.635,-3.35) 4(0.635,-3.35)
S4P_PC-2.6x4.55?2.1-PX1.27-PY7+7 [mm] "KC00080BKP"
  rect 0.6x1.3 smd paste-1.3 mask+0: 1(0.635,3.35) 2(-0.65,3.35) 3(-0.635,-3.35) 4(0.635,-3.35)
S4P_PC-2.6x4.55?2.1-PX1.27-PY7+8 [mm] "KC00080BKP"
  rect 0.6x1.3 smd paste-1.3 mask+0: 1(0.635,3.35) 2(-0.65,3.35) 3(-0.635,-3.35) 4(0.635,-3.35)
S4P_PC-2.6x4.55?2.1-PX1.27-PY7+9 [mm] "KC00080BKP"
  rect 0.6x1.3 smd paste-1.3 mask+0: 1(0.635,3.35) 2(-0.65,3.35) 3(-0.635,-3.35) 4(0.635,-3.35)
S4P_PC-2.6x4.55?2.1-PX1.27-PY7+10 [mm] "KC00080BKP"
  rect 0.6x1.3 smd paste-1.3 mask+0: 1(0.635,3.35) 2(-0.65,3.35) 3(-0.635,-3.35) 4(0.635,-3.35)
S4P_PC-2.6x4.55?2.1-PX1.27-PY7+11 [mm] "KC00080BKP"
  rect 0.6x1.3 smd paste-1.3 mask+0: 1(0.635,3.35) 2(-0.65,3.35) 3(-0.635,-3.35) 4(0.635,-3.35)
S4P_PC-2.6x4.55?2.1-PX1.27-PY7+12 [mm] "KC00080BKP"
  rect 0.6x1.3 smd paste-1.3 mask+0: 1(0.635,3.35) 2(-0.65,3.35) 3(-0.635,-3.35) 4(0.635,-3.35)
S4P_PC-2.6x4.55?2.1-PX1.27-PY7+13 [mm] "KC00080BKP"
  rect 0.6x1.3 smd paste-1.3 mask+0: 1(0.635,3.35) 2(-0.65,3.35) 3(-0.635,-3.35) 4(0.635,-3.35)
S4P_PC-2.6x4.55?2.1-PX1.27-PY7+14 [mm] "KC00080BKP"
  rect 0.6x1.3 smd paste-1.3 mask+0: 1(0.635,3.35) 2(-0.65,3.35) 3(-0.635,-3.35) 4(0.635,-3.35)
S4P_PC-2.6x4.55?2.1-PX1.27-PY7+15 [mm] "KC00080BKP"
  rect 0.6x1.3 smd paste-1.3 mask+0: 1(0.635,3.35) 2(-0.65,3.35) 3(-0.635,-3.35) 4(0.635,-3.35)
S4P_PC-3.7?4.55?2.1-PX2.54-PY7 [mm] "KC00080BKP"
  rect 0.6x1.3 smd paste-1.3 mask+0: 1(1.27,3.35) 3(-1.285,3.35) 4(-1.27,-3.35) 6(1.27,-3.35)
S4P_PC-3.7?4.55?2.1-PX2.54-PY7+1 [mm] "KC00080BKP"
  rect 0.6x1.3 smd paste-1.3 mask+0: 1(1.27,3.35) 3(-1.285,3.35) 4(-1.27,-3.35) 6(1.27,-3.35)
S4P_PC-3.7?4.55?2.1-PX2.54-PY7+2 [mm] "KC00080BKP"
  rect 0.6x1.3 smd paste-1.3 mask+0: 1(1.27,3.35) 3(-1.285,3.35) 4(-1.27,-3.35) 6(1.27,-3.35)
S4P_PC-3.7?4.55?2.1-PX2.54-PY7+3 [mm] "KC00080BKP"
  rect 0.6x1.3 smd paste-1.3 mask+0: 1(1.27,3.35) 3(-1.285,3.35) 4(-1.27,-3.35) 6(1.27,-3.35)
S4P_PC-3.7?4.55?2.1-PX2.54-PY7+4 [mm] "KC00080BKP"
  rect 0.6x1.3 smd paste-1.3 mask+0: 1(1.27,3.35) 3(-1.285,3.35) 4(-1.27,-3.35) 6(1.27,-3.35)
S4P_PC-3.7?4.55?2.1-PX2.54-PY7+5 [mm] "KC00080BKP"
  rect 0.6x1.3 smd paste-1.3 mask+0: 1(1.27,3.35) 3(-1.285,3.35) 4(-1.27,-3.35) 6(1.27,-3.35)
S4P_PC-3.7?4.55?2.1-PX2.54-PY7+6 [mm] "KC00080BKP"
  rect 0.6x1.3 smd paste-1.3 mask+0: 1(1.27,3.35) 3(-1.285,3.35) 4(-1.27,-3.35) 6(1.27,-3.35)
S4P_PC-3.7?4.55?2.1-PX2.54-PY7+7 [mm] "KC00080BKP"
  rect 0.6x1.3 smd paste-1.3 mask+0: 1(1.27,3.35) 3(-1.285,3.35) 4(-1.27,-3.35) 6(1.27,-3.35)
S4P_PC-3.7?4.55?2.1-PX2.54-PY7+8 [mm] "KC00080BKP"
  rect 0.6x1.3 smd paste-1.3 mask+0: 1(1.27,3.35) 3(-1.285,3.35) 4(-1.27,-3.35) 6(1.27,-3.35)
S4P_PC-3.7?4.55?2.1-PX2.54-PY7+9 [mm] "KC00080BKP"
  rect 0.6x1.3 smd paste-1.3 mask+0: 1(1.27,3.35) 3(-1.285,3.35) 4(-1.27,-3.35) 6(1.27,-3.35)
S4P_PC-3.7?4.55?2.1-PX2.54-PY7+10 [mm] "KC00080BKP"
  rect 0.6x1.3 smd paste-1.3 mask+0: 1(1.27,3.35) 3(-1.285,3.35) 4(-1.27,-3.35) 6(1.27,-3.35)
S4P_PC-3.7?4.55?2.1-PX2.54-PY7+11 [mm] "KC00080BKP"
  rect 0.6x1.3 smd paste-1.3 mask+0: 1(1.27,3.35) 3(-1.285,3.35) 4(-1.27,-3.35) 6(1.27,-3.35)
S6P_U-2x1.25x0.95-PX0.65-PY2.1 [mm] "KC00080BKP"
  rect 0.45x1.05 smd paste-1.05 mask+0: 1(0.65,1.025) 2(0,1.025) 3(-0.65,1.025) 4(-0.65,-1.025) 5(0,-1.025) 6(0.65,-1.025)
S6P_U-2x1.25x0.95-PX0.65-PY2.1+1 [mm] "KC00080BKP"
  rect 0.45x1.05 smd paste-1.05 mask+0: 1(0.65,1.025) 2(0,1.025) 3(-0.65,1.025) 4(-0.65,-1.025) 5(0,-1.025) 6(0.65,-1.025)
S6P_U-2x1.25x0.95-PX0.65-PY2.1+2 [mm] "KC00080BKP"
  rect 0.45x1.05 smd paste-1.05 mask+0: 1(0.65,1.025) 2(0,1.025) 3(-0.65,1.025) 4(-0.65,-1.025) 5(0,-1.025) 6(0.65,-1.025)
S6P_U-2x1.25x0.95-PX0.65-PY2.1+3 [mm] "KC00080BKP"
  rect 0.45x1.05 smd paste-1.05 mask+0: 1(0.65,1.025) 2(0,1.025) 3(-0.65,1.025) 4(-0.65,-1.025) 5(0,-1.025) 6(0.65,-1.025)
S6P_U-2x1.25x0.95-PX0.65-PY2.1+4 [mm] "KC00080BKP"
  rect 0.45x1.05 smd paste-1.05 mask+0: 1(0.65,1.025) 2(0,1.025) 3(-0.65,1.025) 4(-0.65,-1.025) 5(0,-1.025) 6(0.65,-1.025)
S6P_U-2x1.25x0.95-PX0.65-PY2.1+5 [mm] "KC00080BKP"
  rect 0.45x1.05 smd paste-1.05 mask+0: 1(0.65,1.025) 2(0,1.025) 3(-0.65,1.025) 4(-0.65,-1.025) 5(0,-1.025) 6(0.65,-1.025)
S6P_U-2x1.25x0.95-PX0.65-PY2.1+6 [mm] "KC00080BKP"
  rect 0.45x1.05 smd paste-1.05 mask+0: 1(0.65,1.025) 2(0,1.025) 3(-0.65,1.025) 4(-0.65,-1.025) 5(0,-1.025) 6(0.65,-1.025)
S6P_U-2x1.25x0.95-PX0.65-PY2.1+7 [mm] "KC00080BKP"
  rect 0.45x1.05 smd paste-1.05 mask+0: 1(0.65,1.025) 2(0,1.025) 3(-0.65,1.025) 4(-0.65,-1.025) 5(0,-1.025) 6(0.65,-1.025)
S8P_U-4.4x3x1.2-PX6.4-PY0.65 [mm] "KC00080BKP"
  rect 1.2x0.35 smd paste-1.2 mask+0: 1(3.1,-0.975) 2(3.1,-0.325) 3(3.1,0.325) 4(3.1,0.975) 5(-3.1,0.975) 6(-3.1,0.325) 7(-3.1,-0.325) 8(-3.1,-0.975)
S8P_U-4.4x3x1.2-PX6.4-PY0.65+1 [mm] "KC00080BKP"
  rect 1.2x0.35 smd paste-1.2 mask+0: 1(3.1,-0.975) 2(3.1,-0.325) 3(3.1,0.325) 4(3.1,0.975) 5(-3.1,0.975) 6(-3.1,0.325) 7(-3.1,-0.325) 8(-3.1,-0.975)
S8P_U-4.4x3x1.2-PX6.4-PY0.65+2 [mm] "KC00080BKP"
  rect 1.2x0.35 smd paste-1.2 mask+0: 1(3.1,-0.975) 2(3.1,-0.325) 3(3.1,0.325) 4(3.1,0.975) 5(-3.1,0.975) 6(-3.1,0.325) 7(-3.1,-0.325) 8(-3.1,-0.975)
S8P_U-4.4x3x1.2-PX6.4-PY0.65+3 [mm] "KC00080BKP"
  rect 1.2x0.35 smd paste-1.2 mask+0: 1(3.1,-0.975) 2(3.1,-0.325) 3(3.1,0.325) 4(3.1,0.975) 5(-3.1,0.975) 6(-3.1,0.325) 7(-3.1,-0.325) 8(-3.1,-0.975)
S8P_U-4.9x3.9x1.75-PX1.27-PY6 [mm] "KC00080BKP"
  rect 0.6x1.2 smd paste-1.2 mask+0: 1(-1.905,-2.9) 2(-0.635,-2.9) 3(0.635,-2.9) 4(1.905,-2.9) 5(1.905,2.9) 6(0.635,2.9) 7(-0.635,2.9) 8(-1.905,2.9)
S8P_U-4.9x3.9x1.75-PX1.27-PY6+1 [mm] "KC00080BKP"
  rect 0.6x1.2 smd paste-1.2 mask+0: 1(-1.905,-2.9) 2(-0.635,-2.9) 3(0.635,-2.9) 4(1.905,-2.9) 5(1.905,2.9) 6(0.635,2.9) 7(-0.635,2.9) 8(-1.905,2.9)
S8P_U-4.9x3.9x1.75-PX1.27-PY6+2 [mm] "KC00080BKP"
  rect 0.6x1.2 smd paste-1.2 mask+0: 1(-1.905,-2.9) 2(-0.635,-2.9) 3(0.635,-2.9) 4(1.905,-2.9) 5(1.905,2.9) 6(0.635,2.9) 7(-0.635,2.9) 8(-1.905,2.9)
S8P_U-4.9x3.9x1.75-PX1.27-PY6+3 [mm] "KC00080BKP"
  rect 0.6x1.2 smd paste-1.2 mask+0: 1(-1.905,-2.9) 2(-0.635,-2.9) 3(0.635,-2.9) 4(1.905,-2.9) 5(1.905,2.9) 6(0.635,2.9) 7(-0.635,2.9) 8(-1.905,2.9)
S9P_U-4.9x3.9x1.7-PX1.27-PY6 [mm] "KC00080BKP"
  rect 0.6x1.3 smd paste-1.3 mask+0: 1(-1.905,-2.85) 2(-0.635,-2.85) 3(0.635,-2.85) 4(1.905,-2.85) 5(1.905,2.85) 6(0.635,2.85) 7(-0.635,2.85) 8(-1.905,2.85)
  rect 4.4x2 smd paste-4.4 mask+0: 9(-0.75,0)
S9P_U-4.9x3.9x1.7-PX1.27-PY6+1 [mm] "KC00080BKP"
  rect 0.6x1.3 smd paste-1.3 mask+0: 1(-1.905,-2.85) 2(-0.635,-2.85) 3(0.635,-2.85) 4(1.905,-2.85) 5(1.905,2.85) 6(0.635,2.85) 7(-0.635,2.85) 8(-1.905,2.85)
  rect 4.4x2 smd paste-4.4 mask+0: 9(-0.75,0)
S9P_U-4.9x3.9x1.7-PX1.27-PY6+2 [mm] "KC00080BKP"
  rect 0.6x1.3 smd paste-1.3 mask+0: 1(-1.905,-2.85) 2(-0.635,-2.85) 3(0.635,-2.85) 4(1.905,-2.85) 5(1.905,2.85) 6(0.635,2.85) 7(-0.635,2.85) 8(-1.905,2.85)
  rect 4.4x2 smd paste-4.4 mask+0: 9(-0.75,0)
S9P_U-4.9x3.9x1.7-PX1.27-PY6+3 [mm] "KC00080BKP"
  rect 0.6x1.3 smd paste-1.3 mask+0: 1(-1.905,-2.85) 2(-0.635,-2.85) 3(0.635,-2.85) 4(1.905,-2.85) 5(1.905,2.85) 6(0.635,2.85) 7(-0.635,2.85) 8(-1.905,2.85)
  rect 4.4x2 smd paste-4.4 mask+0: 9(-0.75,0)
S16P_U-5x4.4x1.2-PX0.65-PY6.4 [mm] "KC00080BKP"
  rect 0.4x1.3 smd paste-1.3 mask+0: 1(2.275,3.05) 2(1.625,3.05) 3(0.975,3.05) 4(0.325,3.05) 5(-0.325,3.05) 6(-0.975,3.05) 7(-1.625,3.05) 8(-2.275,3.05) 9(-2.275,-3.05) 10(-1.625,-3.05) 11(-0.975,-3.05) 12(-0.325,-3.05) 13(0.325,-3.05) 14(0.975,-3.05) 15(1.625,-3.05) 16(2.275,-3.05)
S16P_U-5x4.4x1.2-PX0.65-PY6.4+1 [mm] "KC00080BKP"
  rect 0.4x1.3 smd paste-1.3 mask+0: 1(2.275,3.05) 2(1.625,3.05) 3(0.975,3.05) 4(0.325,3.05) 5(-0.325,3.05) 6(-0.975,3.05) 7(-1.625,3.05) 8(-2.275,3.05) 9(-2.275,-3.05) 10(-1.625,-3.05) 11(-0.975,-3.05) 12(-0.325,-3.05) 13(0.325,-3.05) 14(0.975,-3.05) 15(1.625,-3.05) 16(2.275,-3.05)
S16P_U-5x4.4x1.2-PX0.65-PY6.4+2 [mm] "KC00080BKP"
  rect 0.4x1.3 smd paste-1.3 mask+0: 1(2.275,3.05) 2(1.625,3.05) 3(0.975,3.05) 4(0.325,3.05) 5(-0.325,3.05) 6(-0.975,3.05) 7(-1.625,3.05) 8(-2.275,3.05) 9(-2.275,-3.05) 10(-1.625,-3.05) 11(-0.975,-3.05) 12(-0.325,-3.05) 13(0.325,-3.05) 14(0.975,-3.05) 15(1.625,-3.05) 16(2.275,-3.05)
S16P_U-5x4.4x1.2-PX0.65-PY6.4+3 [mm] "KC00080BKP"
  rect 0.4x1.3 smd paste-1.3 mask+0: 1(2.275,3.05) 2(1.625,3.05) 3(0.975,3.05) 4(0.325,3.05) 5(-0.325,3.05) 6(-0.975,3.05) 7(-1.625,3.05) 8(-2.275,3.05) 9(-2.275,-3.05) 10(-1.625,-3.05) 11(-0.975,-3.05) 12(-0.325,-3.05) 13(0.325,-3.05) 14(0.975,-3.05) 15(1.625,-3.05) 16(2.275,-3.05)

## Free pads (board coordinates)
  round 0 hole 3.5 unplated paste-3.7 mask+0: ""(25,25) ""(25,145) ""(25,265) ""(194,25) ""(194,145) ""(194,265) ""(248,85) ""(248,205) ""(307,25) ""(307,145) ""(307,265) ""(345,25) ""(345,145) ""(345,265)
  round 0.6 smd far side paste-0.6 mask+0: ""(53.5,119.75) ""(62.875,114.5) ""(97.27,89.625) ""(97.27,149.625) ""(97.27,209.625) ""(102.27,89.625) ""(102.27,149.625) ""(102.27,209.625) ""(107.27,89.625) ""(107.27,149.625) ""(107.27,209.625) ""(176,164.375) ""(183,164.375) ""(186.5,174) ""(190,164.375) ""(193.375,92.75) ""(193.375,95.75)
  round 0 hole 3 square unplated paste-8 mask+0: ""(85,282.5) ""(125,282.5) ""(165,274.5) ""(205,274.5) ""(245,282.5) ""(285,282.5)
  round 0 hole 10.5 unplated paste-10.5 mask+0: ""(105,303) ""(185,295) ""(265,303)
  round 0.6 smd paste-0.6 mask+0: ""(172.25,218.75) ""(183,164.375) ""(190,164.375)

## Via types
v1: diameter 0.8, hole 0.3, TOP to BOTTOM, 12534 vias

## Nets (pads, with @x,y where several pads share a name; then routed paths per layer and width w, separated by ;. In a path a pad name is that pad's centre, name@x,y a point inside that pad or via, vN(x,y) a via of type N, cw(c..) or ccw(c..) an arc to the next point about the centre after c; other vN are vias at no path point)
$BN000001: C444.1 D322.1 R434.2 | length 4
  TOP w0.5: C444.1@52.385,242.625 52.487,242.727 D322.1@54.075,242.727 54.075,243.68 53.875,243.88 R434.2@53.875,244.95
$BN000002: C445.1 D323.1 R435.2 | length 4
  TOP w0.5: C445.1@52.385,182.618 52.487,182.72 D323.1@54.075,182.72 54.075,183.736 53.875,183.936 R435.2@53.875,184.942
$BN000003: C446.1 D324.1 R436.2 | length 4
  TOP w0.5: C446.1@52.385,122.61 52.487,122.712 D324.1@54.075,122.712 54.075,123.792 53.875,123.992 R436.2@53.875,124.935
$BN000004: C447.1 D325.1 R437.2 | length 4
  TOP w0.5: C447.1@52.385,62.603 52.487,62.705 D325.1@54.075,62.705 54.075,63.848 53.875,64.048 R437.2@53.875,64.927
DIAG_0-1: CN3.6 PC7.4 | length 7.3
  TOP w0.25: CN3.6@273.5,203.5 273.5,208.885 v1(273.865,209.25)
  BOTTOM w0.25: v1(273.865,209.25) PC7.4@273.865,210.65
DIAG_0-2: CN103.6 PC107.4 | length 7.3
  TOP w0.25: CN103.6@273.5,143.5 273.5,148.885 v1(273.865,149.25)
  BOTTOM w0.25: v1(273.865,149.25) PC107.4@273.865,150.65
DIAG_0-3: CN203.6 PC207.4 | length 7.3
  TOP w0.25: CN203.6@273.5,83.5 273.5,88.885 v1(273.865,89.25)
  BOTTOM w0.25: v1(273.865,89.25) PC207.4@273.865,90.65
DIAG_0-4: CN303.6 PC307.4 | length 7.3
  TOP w0.25: CN303.6@273.5,23.5 273.5,28.885 v1(273.865,29.25)
  BOTTOM w0.25: v1(273.865,29.25) PC307.4@273.865,30.65
GND-1: C72.2 C73.2 C74.2 C75.2 C77.1 C78.1 C100.1 CN1.3 CN2.9 CN3.3 CN4.4 IC11.4 IC14.4 PC2.3 PC7.3 Q18.1 Q18.4 Q19.1 Q19.4 | length 81.2
  TOP w0.25: IC14.4@182.1,213.845 183.075,213.845 ; 183.85,218.975 C100.1@183.85,219.75
  TOP w0.5: 100.975,203.225 CN4.4@102,204.25 ; 100.975,205.275 CN4.4@102,204.25 ; 103.025,203.225 CN4.4@102,204.25 ; 103.025,205.275 CN4.4@102,204.25 ; 133.975,202.475 CN2.9@135,203.5 ; 133.975,204.525 CN2.9@135,203.5 ; 136.025,202.475 CN2.9@135,203.5 ; 136.025,204.525 CN2.9@135,203.5 ; 166.225,203.475 CN1.3@167.25,204.5 ; 166.25,205.5 CN1.3@167.25,204.5 ; 168.25,205.5 CN1.3@167.25,204.5 ; 168.275,203.475 CN1.3@167.25,204.5
  Mid-Layer 1 w0.5: 100.975,203.225 CN4.4@102,204.25 ; 100.975,205.275 CN4.4@102,204.25 ; 103.025,203.225 CN4.4@102,204.25 ; 103.025,205.275 CN4.4@102,204.25 ; 133.975,202.475 CN2.9@135,203.5 ; 133.975,204.525 CN2.9@135,203.5 ; 136.025,202.475 CN2.9@135,203.5 ; 136.025,204.525 CN2.9@135,203.5 ; 166.225,203.475 CN1.3@167.25,204.5 ; 166.225,205.525 CN1.3@167.25,204.5 ; 168.275,203.475 CN1.3@167.25,204.5 ; 168.275,205.525 CN1.3@167.25,204.5
  BOTTOM w0.25: 92.135,209.875 PC2.3@92.135,210.9 ; 92.135,211.925 PC2.3@92.135,210.9 ; 92.81,210.9 PC2.3@92.135,210.9 ; 109.725,206.5 Q18.1@109.725,207.1 110.625,207.1 ; 110.875,208.4 Q18.4@111.775,208.4 ; 111.075,204.25 C78.1@112.025,204.25 ; 111.775,209 Q18.4@111.775,208.4 ; 112.025,202.525 C78.1@112.025,204.25 ; 112.025,205.975 C78.1@112.025,204.25 ; 112.675,208.4 Q18.4@111.775,208.4 ; 112.975,204.25 C78.1@112.025,204.25 ; 118.025,214 C77.1@118.85,214 ; 118.85,213.225 C77.1@118.85,214 ; 118.85,214.775 C77.1@118.85,214 ; 120.375,210.025 IC11.4@121.35,210.025 121.35,209.475 ; 275.135,209.625 PC7.3@275.135,210.65 275.81,210.65 ; 275.225,205.75 Q19.4@275.225,206.35 276.125,206.35 ; 276.375,207.65 Q19.1@277.275,207.65 ; 277.275,208.25 Q19.1@277.275,207.65 ; 278.175,207.65 Q19.1@277.275,207.65
  BOTTOM w0.5: 100.975,203.225 CN4.4@102,204.25 ; 100.975,205.275 CN4.4@102,204.25 ; 103.025,203.225 CN4.4@102,204.25 ; 103.025,205.275 CN4.4@102,204.25 ; 133.975,202.475 CN2.9@135,203.5 ; 133.975,204.525 CN2.9@135,203.5 ; 136.025,202.475 CN2.9@135,203.5 ; 136.025,204.525 CN2.9@135,203.5 ; 166.225,203.475 CN1.3@167.25,204.5 ; 166.225,205.525 CN1.3@167.25,204.5 ; 168.275,203.475 CN1.3@167.25,204.5 ; 168.275,205.525 CN1.3@167.25,204.5 ; 279.975,202.475 CN3.3@281,203.5 ; 279.975,204.525 CN3.3@281,203.5 ; 282.025,202.475 CN3.3@281,203.5 ; 282.025,204.525 CN3.3@281,203.5
  other v1: 183.85,213.845
GND-2: C110.1 C172.2 C173.2 C174.2 C175.2 C177.1 C178.1 CN101.3 CN102.9 CN103.3 CN104.4 IC111.4 IC114.4 PC102.3 PC107.3 Q118.1 Q118.4 Q119.1 Q119.4 | length 81.2
  TOP w0.25: IC114.4@182.1,153.845 183.075,153.845 ; 183.85,158.975 C110.1@183.85,159.75
  TOP w0.5: 100.975,143.225 CN104.4@102,144.25 ; 100.975,145.275 CN104.4@102,144.25 ; 103.025,143.225 CN104.4@102,144.25 ; 103.025,145.275 CN104.4@102,144.25 ; 133.975,142.475 CN102.9@135,143.5 ; 133.975,144.525 CN102.9@135,143.5 ; 136.025,142.475 CN102.9@135,143.5 ; 136.025,144.525 CN102.9@135,143.5 ; 166.225,143.475 CN101.3@167.25,144.5 ; 166.25,145.5 CN101.3@167.25,144.5 ; 168.25,145.5 CN101.3@167.25,144.5 ; 168.275,143.475 CN101.3@167.25,144.5
  Mid-Layer 1 w0.5: 100.975,143.225 CN104.4@102,144.25 ; 100.975,145.275 CN104.4@102,144.25 ; 103.025,143.225 CN104.4@102,144.25 ; 103.025,145.275 CN104.4@102,144.25 ; 133.975,142.475 CN102.9@135,143.5 ; 133.975,144.525 CN102.9@135,143.5 ; 136.025,142.475 CN102.9@135,143.5 ; 136.025,144.525 CN102.9@135,143.5 ; 166.225,143.475 CN101.3@167.25,144.5 ; 166.225,145.525 CN101.3@167.25,144.5 ; 168.275,143.475 CN101.3@167.25,144.5 ; 168.275,145.525 CN101.3@167.25,144.5
  BOTTOM w0.25: 92.135,149.875 PC102.3@92.135,150.9 ; 92.135,151.925 PC102.3@92.135,150.9 ; 92.81,150.9 PC102.3@92.135,150.9 ; 109.725,146.5 Q118.1@109.725,147.1 110.625,147.1 ; 110.875,148.4 Q118.4@111.775,148.4 ; 111.075,144.25 C178.1@112.025,144.25 ; 111.775,149 Q118.4@111.775,148.4 ; 112.025,142.525 C178.1@112.025,144.25 ; 112.025,145.975 C178.1@112.025,144.25 ; 112.675,148.4 Q118.4@111.775,148.4 ; 112.975,144.25 C178.1@112.025,144.25 ; 118.025,154 C177.1@118.85,154 ; 118.85,153.225 C177.1@118.85,154 ; 118.85,154.775 C177.1@118.85,154 ; 120.375,150.025 IC111.4@121.35,150.025 121.35,149.475 ; 275.135,149.625 PC107.3@275.135,150.65 275.81,150.65 ; 275.225,145.75 Q119.4@275.225,146.35 276.125,146.35 ; 276.375,147.65 Q119.1@277.275,147.65 ; 277.275,148.25 Q119.1@277.275,147.65 ; 278.175,147.65 Q119.1@277.275,147.65
  BOTTOM w0.5: 100.975,143.225 CN104.4@102,144.25 ; 100.975,145.275 CN104.4@102,144.25 ; 103.025,143.225 CN104.4@102,144.25 ; 103.025,145.275 CN104.4@102,144.25 ; 133.975,142.475 CN102.9@135,143.5 ; 133.975,144.525 CN102.9@135,143.5 ; 136.025,142.475 CN102.9@135,143.5 ; 136.025,144.525 CN102.9@135,143.5 ; 166.225,143.475 CN101.3@167.25,144.5 ; 166.225,145.525 CN101.3@167.25,144.5 ; 168.275,143.475 CN101.3@167.25,144.5 ; 168.275,145.525 CN101.3@167.25,144.5 ; 279.975,142.475 CN103.3@281,143.5 ; 279.975,144.525 CN103.3@281,143.5 ; 282.025,142.475 CN103.3@281,143.5 ; 282.025,144.525 CN103.3@281,143.5
  other v1: 183.85,153.845
GND-3: C210.1 C272.2 C273.2 C274.2 C275.2 C277.1 C278.1 CN201.3 CN202.9 CN203.3 CN204.4 IC211.4 IC214.4 PC202.3 PC207.3 Q218.1 Q218.4 Q219.1 Q219.4 | length 81.2
  TOP w0.25: IC214.4@182.1,93.845 183.075,93.845 ; 183.85,98.975 C210.1@183.85,99.75
  TOP w0.5: 100.975,83.225 CN204.4@102,84.25 ; 100.975,85.275 CN204.4@102,84.25 ; 103.025,83.225 CN204.4@102,84.25 ; 103.025,85.275 CN204.4@102,84.25 ; 133.975,82.475 CN202.9@135,83.5 ; 133.975,84.525 CN202.9@135,83.5 ; 136.025,82.475 CN202.9@135,83.5 ; 136.025,84.525 CN202.9@135,83.5 ; 166.225,83.475 CN201.3@167.25,84.5 ; 166.25,85.5 CN201.3@167.25,84.5 ; 168.25,85.5 CN201.3@167.25,84.5 ; 168.275,83.475 CN201.3@167.25,84.5
  Mid-Layer 1 w0.5: 100.975,83.225 CN204.4@102,84.25 ; 100.975,85.275 CN204.4@102,84.25 ; 103.025,83.225 CN204.4@102,84.25 ; 103.025,85.275 CN204.4@102,84.25 ; 133.975,82.475 CN202.9@135,83.5 ; 133.975,84.525 CN202.9@135,83.5 ; 136.025,82.475 CN202.9@135,83.5 ; 136.025,84.525 CN202.9@135,83.5 ; 166.225,83.475 CN201.3@167.25,84.5 ; 166.225,85.525 CN201.3@167.25,84.5 ; 168.275,83.475 CN201.3@167.25,84.5 ; 168.275,85.525 CN201.3@167.25,84.5
  BOTTOM w0.25: 92.135,89.875 PC202.3@92.135,90.9 ; 92.135,91.925 PC202.3@92.135,90.9 ; 92.81,90.9 PC202.3@92.135,90.9 ; 109.725,86.5 Q218.1@109.725,87.1 110.625,87.1 ; 110.875,88.4 Q218.4@111.775,88.4 ; 111.075,84.25 C278.1@112.025,84.25 ; 111.775,89 Q218.4@111.775,88.4 ; 112.025,82.525 C278.1@112.025,84.25 ; 112.025,85.975 C278.1@112.025,84.25 ; 112.675,88.4 Q218.4@111.775,88.4 ; 112.975,84.25 C278.1@112.025,84.25 ; 118.025,94 C277.1@118.85,94 ; 118.85,93.225 C277.1@118.85,94 ; 118.85,94.775 C277.1@118.85,94 ; 120.375,90.025 IC211.4@121.35,90.025 121.35,89.475 ; 275.135,89.625 PC207.3@275.135,90.65 275.81,90.65 ; 275.225,85.75 Q219.4@275.225,86.35 276.125,86.35 ; 276.375,87.65 Q219.1@277.275,87.65 ; 277.275,88.25 Q219.1@277.275,87.65 ; 278.175,87.65 Q219.1@277.275,87.65
  BOTTOM w0.5: 100.975,83.225 CN204.4@102,84.25 ; 100.975,85.275 CN204.4@102,84.25 ; 103.025,83.225 CN204.4@102,84.25 ; 103.025,85.275 CN204.4@102,84.25 ; 133.975,82.475 CN202.9@135,83.5 ; 133.975,84.525 CN202.9@135,83.5 ; 136.025,82.475 CN202.9@135,83.5 ; 136.025,84.525 CN202.9@135,83.5 ; 166.225,83.475 CN201.3@167.25,84.5 ; 166.225,85.525 CN201.3@167.25,84.5 ; 168.275,83.475 CN201.3@167.25,84.5 ; 168.275,85.525 CN201.3@167.25,84.5 ; 279.975,82.475 CN203.3@281,83.5 ; 279.975,84.525 CN203.3@281,83.5 ; 282.025,82.475 CN203.3@281,83.5 ; 282.025,84.525 CN203.3@281,83.5
  other v1: 183.85,93.845
GND-4: C310.1 C372.2 C373.2 C374.2 C375.2 C377.1 C378.1 CN301.3 CN302.9 CN303.3 CN304.4 IC311.4 IC314.4 PC302.3 PC307.3 Q318.1 Q318.4 Q319.1 Q319.4 | length 81.2
  TOP w0.25: IC314.4@182.1,33.845 183.075,33.845 ; 183.85,38.975 C310.1@183.85,39.75
  TOP w0.5: 100.975,23.225 CN304.4@102,24.25 ; 100.975,25.275 CN304.4@102,24.25 ; 103.025,23.225 CN304.4@102,24.25 ; 103.025,25.275 CN304.4@102,24.25 ; 133.975,22.475 CN302.9@135,23.5 ; 133.975,24.525 CN302.9@135,23.5 ; 136.025,22.475 CN302.9@135,23.5 ; 136.025,24.525 CN302.9@135,23.5 ; 166.225,23.475 CN301.3@167.25,24.5 ; 166.25,25.5 CN301.3@167.25,24.5 ; 168.25,25.5 CN301.3@167.25,24.5 ; 168.275,23.475 CN301.3@167.25,24.5
  Mid-Layer 1 w0.5: 100.975,23.225 CN304.4@102,24.25 ; 100.975,25.275 CN304.4@102,24.25 ; 103.025,23.225 CN304.4@102,24.25 ; 103.025,25.275 CN304.4@102,24.25 ; 133.975,22.475 CN302.9@135,23.5 ; 133.975,24.525 CN302.9@135,23.5 ; 136.025,22.475 CN302.9@135,23.5 ; 136.025,24.525 CN302.9@135,23.5 ; 166.225,23.475 CN301.3@167.25,24.5 ; 166.225,25.525 CN301.3@167.25,24.5 ; 168.275,23.475 CN301.3@167.25,24.5 ; 168.275,25.525 CN301.3@167.25,24.5
  BOTTOM w0.25: 92.135,29.875 PC302.3@92.135,30.9 ; 92.135,31.925 PC302.3@92.135,30.9 ; 92.81,30.9 PC302.3@92.135,30.9 ; 109.725,26.5 Q318.1@109.725,27.1 110.625,27.1 ; 110.875,28.4 Q318.4@111.775,28.4 ; 111.075,24.25 C378.1@112.025,24.25 ; 111.775,29 Q318.4@111.775,28.4 ; 112.025,22.525 C378.1@112.025,24.25 ; 112.025,25.975 C378.1@112.025,24.25 ; 112.675,28.4 Q318.4@111.775,28.4 ; 112.975,24.25 C378.1@112.025,24.25 ; 118.025,34 C377.1@118.85,34 ; 118.85,33.225 C377.1@118.85,34 ; 118.85,34.775 C377.1@118.85,34 ; 120.375,30.025 IC311.4@121.35,30.025 121.35,29.475 ; 275.135,29.625 PC307.3@275.135,30.65 275.81,30.65 ; 275.225,25.75 Q319.4@275.225,26.35 276.125,26.35 ; 276.375,27.65 Q319.1@277.275,27.65 ; 277.275,28.25 Q319.1@277.275,27.65 ; 278.175,27.65 Q319.1@277.275,27.65
  BOTTOM w0.5: 100.975,23.225 CN304.4@102,24.25 ; 100.975,25.275 CN304.4@102,24.25 ; 103.025,23.225 CN304.4@102,24.25 ; 103.025,25.275 CN304.4@102,24.25 ; 133.975,22.475 CN302.9@135,23.5 ; 133.975,24.525 CN302.9@135,23.5 ; 136.025,22.475 CN302.9@135,23.5 ; 136.025,24.525 CN302.9@135,23.5 ; 166.225,23.475 CN301.3@167.25,24.5 ; 166.225,25.525 CN301.3@167.25,24.5 ; 168.275,23.475 CN301.3@167.25,24.5 ; 168.275,25.525 CN301.3@167.25,24.5 ; 279.975,22.475 CN303.3@281,23.5 ; 279.975,24.525 CN303.3@281,23.5 ; 282.025,22.475 CN303.3@281,23.5 ; 282.025,24.525 CN303.3@281,23.5
  other v1: 183.85,33.845
GND_5V_I0_0: C98.2 CN27.1 pad.@172.25,218.75 | length 22.6
  TOP w0.5: CN27.1@167.75,220.5 171.75,220.5 172.25,220 v1(172.25,218.75) C98.2@172.25,216.4
  TOP w0.6: v1(185.625,218.75) 186.5,218.75
  BOTTOM w0.5: v1(172.25,218.75) v1(185.625,218.75)
GND_5V_I0_1: C70.2 CN25.1 | length 32.2
  TOP w0.5: v1(282.75,223.625) 282.75,215 283.375,214.375 284.625,214.375 286,213 286,211.5 286.5,211 287,211 ; CN25.1@288.625,210 288.937,210.313 289.5,210.875 289.5,211 ; CN25.1@288.625,212 289.5,211.125 289.5,211 ; C70.2@294.5,210.15 291.85,210.15 291,211 289.5,211 ; 287,211 288,212 288.25,212 CN25.1@288.25,211 ; 287,211 287.625,210.375 288,210 288.25,210 CN25.1@288.25,211 ; 287,211 CN25.1@288.25,211 ; CN25.1@288.25,211 289.5,211
  BOTTOM w0.6: v1(282.75,223.625) 282.75,224.5
GND_5V_I0_2: C97.2 CN26.1 | length 34.7
  TOP w0.5: 70,228.875 70,228.25 70.625,227.625 70.625,205.625 71.25,205 CN26.1@74.5,205 C97.2@81.6,205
